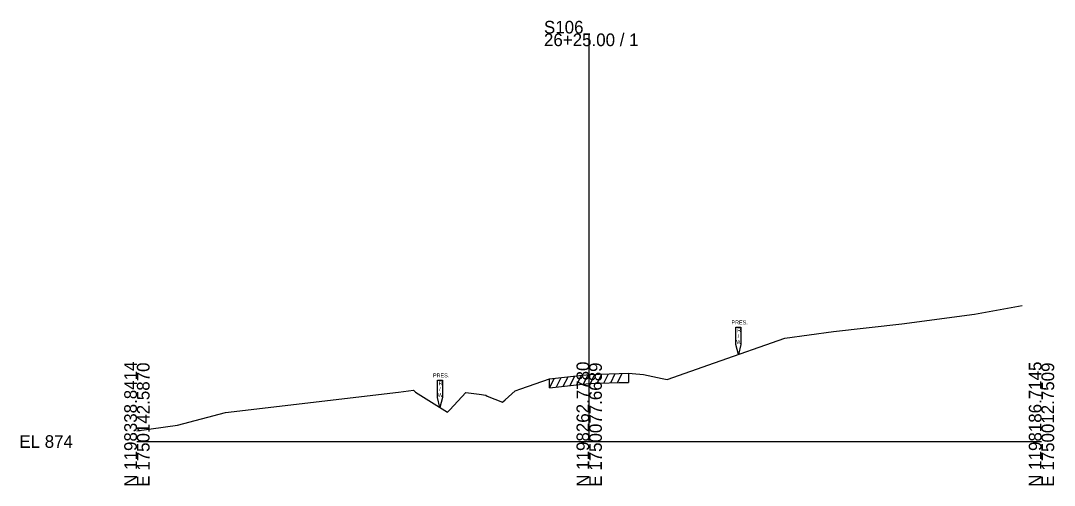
# Model space of a CAD drawing. Extents: x -26 to 1203, y -10 to 19527.
# Drawn here: x -25.7 to 202.8, y 2490.3 to 2593.1 of the extents above; entities that cross this region are included whole.
import ezdxf

# ---------------------------------------------------------------- set-up
doc = ezdxf.new("R2010")
doc.units = 0
for name, color, linetype in [('RD_GPK_XS_Cell', 7, 'Continuous'), ('RD_XS_ExGround', 7, 'Continuous'), ('RD_XS_ExPaveRet', 7, 'Continuous'), ('RD_XS_ExRW', 7, 'Continuous'), ('RD_XS_TX_Elev_EX', 7, 'Continuous')]:
    doc.layers.add(name, color=color, linetype=linetype)

msp = doc.modelspace()

# ---------------------------------------------------------------- linework, layer by layer
at = {"layer": 'RD_GPK_XS_Cell'}
for p, q in [((100, 2500), (100, 2590.29)), ((0, 2500), (100, 2500)), ((100, 2500), (200, 2500))]:
    msp.add_line(p, q, dxfattribs=at)
at = {"layer": 'RD_XS_ExGround'}
msp.add_lwpolyline([(0, 2502.4), (8.99, 2503.65), (19.62, 2506.45), (57.85, 2510.9), (61.15, 2511.36), (61.63, 2510.9), (68.64, 2506.52), (69.16, 2507.01), (72.7, 2510.82), (75.64, 2510.46), (77.14, 2510.28), (77.46, 2510.01), (80.84, 2508.71), (81.4, 2509.2), (83.62, 2511.2), (84.92, 2511.65), (91.26, 2513.9), (97.84, 2514.64), (100.05, 2514.86), (106.66, 2515.04), (108.69, 2515.1), (109.52, 2515.06), (112.01, 2514.85), (116.15, 2513.95), (117.24, 2513.73), (127.67, 2517.38), (143.23, 2522.91), (154.03, 2524.36), (169.09, 2526.03), (185.22, 2528.17), (195.73, 2530.1)], dxfattribs=at)
at = {"layer": 'RD_XS_ExPaveRet'}
for p, q in [((91.26, 2511.9), (92.32, 2514.02)), ((91.26, 2511.9), (91.26, 2513.9)), ((92.76, 2512.07), (93.82, 2514.19)), ((94.26, 2512.23), (95.32, 2514.35)), ((95.76, 2512.4), (96.82, 2514.52)), ((97.26, 2512.57), (98.31, 2514.69)), ((98.76, 2512.73), (99.81, 2514.84)), ((100.26, 2512.87), (101.27, 2514.9)), ((101.76, 2512.91), (102.77, 2514.94)), ((103.26, 2512.95), (104.27, 2514.98)), ((104.76, 2512.99), (105.77, 2515.02)), ((106.26, 2513.03), (107.27, 2515.06)), ((108.69, 2515.1), (108.69, 2513.1)), ((91.26, 2511.9), (97.84, 2512.64)), ((97.84, 2512.64), (100.05, 2512.86)), ((100.05, 2512.86), (106.66, 2513.04)), ((106.66, 2513.04), (108.69, 2513.1))]:
    msp.add_line(p, q, dxfattribs=at)
at = {"layer": 'RD_XS_ExRW'}
for points in [[(132.45, 2525.29), (133.55, 2525.29), (133.55, 2521.46), (133, 2519.27), (132.45, 2521.46)], [(66.45, 2513.56), (67.55, 2513.56), (67.55, 2509.73), (67, 2507.54), (66.45, 2509.73)]]:
    msp.add_lwpolyline(points, close=True, dxfattribs=at)

# ---------------------------------------------------------------- texts
at = {"layer": 'RD_GPK_XS_Cell'}
for s, p in [('S106', (90, 2590.29)), ('26+25.00 / 1', (90, 2587.49)), ('EL 874', (-26, 2498.6))]:
    msp.add_text(s, height=2.8, dxfattribs=at).set_placement(p)
for s, p in [('N 1198338.8414', (0, 2490)), ('E 1750142.5870', (2.8, 2490)), ('N 1198262.7780', (100, 2490)), ('E 1750077.6689', (102.8, 2490)), ('N 1198186.7145', (200, 2490)), ('E 1750012.7509', (202.8, 2490))]:
    msp.add_text(s, height=2.8, rotation=90, dxfattribs=at).set_placement(p)
at = {"layer": 'RD_XS_ExRW'}
for s, p in [('PRES.', (131.45, 2525.92)), ('R', (132.71, 2524.2)), ('/', (132.83, 2522.89)), ('W', (132.53, 2521.57)), ('PRES.', (65.45, 2514.19)), ('R', (66.71, 2512.47)), ('/', (66.83, 2511.16)), ('W', (66.53, 2509.84))]:
    msp.add_text(s, height=0.875, dxfattribs=at).set_placement(p)
at = {"layer": 'RD_XS_TX_Elev_EX'}
msp.add_text('881.43', height=0.0975, rotation=90, dxfattribs=at).set_placement((100.1, 2514.86))

doc.saveas('drawing.dxf')
